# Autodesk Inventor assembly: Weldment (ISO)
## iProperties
Length Units: 11269
Angle Units: 11283
Time Units: 11279
Mass Units: 11290
Length Display Precision: 3
Angle Display Precision: 2
Part Number: Weldment (ISO)
Document SubType Name: Weldment
Created: 2002-06
Designer: smithga
Part Number: Ens_tambour
Created: 2008-02
Designer: Pascal
Material: Aluminum soudé-6061
Control State: 0
Master: False
Shininess: 64.0
Angle Units: 11279
Time Units: 11290
Mass Units: 11283
Compacted: True
DESIGNATION: Tambour type A
Density: 0.0
Volumn: 0.0
Area: 0.0
PropertySet Name: Model Information
Author: Pascal
